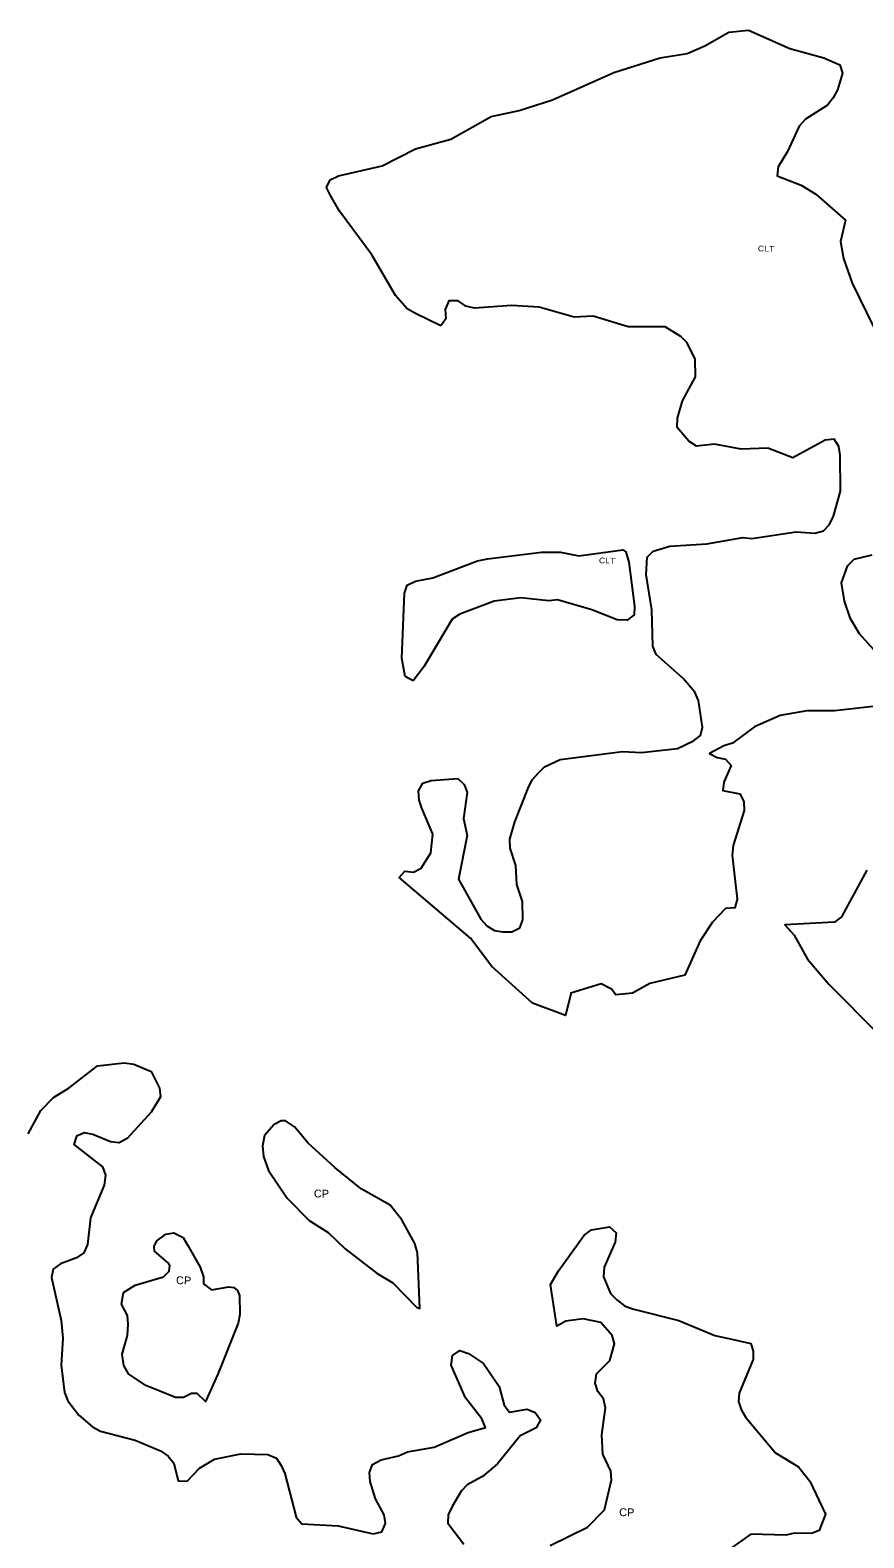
# Model space of a CAD drawing. Extents: x 713589 to 726391, y 7177764 to 7191819.
# Drawn here: x 715078 to 715761, y 7180236 to 7181472 of the extents above; entities that cross this region are included whole.
import ezdxf
from ezdxf.enums import TextEntityAlignment as Align

# ---------------------------------------------------------------- set-up
doc = ezdxf.new("R2010")
doc.units = 0
doc.header["$LTSCALE"] = 2.6
doc.layers.add('63', color=7, linetype='Continuous', lineweight=25)

msp = doc.modelspace()

# ---------------------------------------------------------------- linework, layer by layer
at = {"layer": '63'}
for points in [[(715414.63, 7181229.54), (715393.77, 7181239.84), (715387.14, 7181243.5), (715377.55, 7181254.45), (715358.05, 7181287.96), (715331.6, 7181323.79), (715324.33, 7181336.4), (715321.03, 7181343.03), (715324.02, 7181349.33), (715330.65, 7181352.63), (715366.46, 7181360.85), (715393.99, 7181374.73), (715422.84, 7181382.63), (715456.01, 7181401.14), (715478.88, 7181406.07), (715506.07, 7181414.98), (715556.49, 7181437.43), (715594.29, 7181449.3), (715616.5, 7181452.9), (715631.09, 7181459.18), (715650.66, 7181470.41), (715666.9, 7181472.04), (715700.68, 7181457.07), (715728.51, 7181449.4), (715741.76, 7181443.75), (715743.73, 7181436.79), (715739.73, 7181423.2), (715736.08, 7181416.58), (715731.43, 7181410.62), (715713.51, 7181399.05), (715708.2, 7181393.43), (715698.89, 7181372.57), (715691.24, 7181359.99), (715690.24, 7181352.7), (715710.11, 7181345.04), (715722.03, 7181337.73), (715746.3, 7181316.21), (715742.14, 7181298.78), (715744.77, 7181284.82), (715751.71, 7181264.54), (715769.26, 7181228.97)], [(715489.78, 7180674.55), (715456.36, 7180704.43), (715438.83, 7180727.66), (715380.58, 7180777.47), (715385.23, 7180782.76), (715392.19, 7180781.75), (715398.49, 7180785.06), (715406.47, 7180797.64), (715408.15, 7180812.88), (715399.14, 7180834.2), (715396.75, 7180840.82), (715396.43, 7180848.44), (715399.76, 7180854.73), (715406.72, 7180857.04), (715428.59, 7180858.66), (715433.89, 7180853.68), (715436.2, 7180847.05), (715433.18, 7180825.85), (715436.14, 7180811.92), (715429.12, 7180776.14), (715447.29, 7180743.3), (715452.26, 7180737.99), (715458.55, 7180734), (715465.5, 7180733), (715472.8, 7180732.98), (715479.43, 7180736.29), (715481.76, 7180742.91), (715481.45, 7180757.83), (715476.84, 7180771.75), (715476.2, 7180787.33), (715471.58, 7180801.59), (715471.26, 7180808.88), (715475.27, 7180823.12), (715486.25, 7180850.61), (715489.57, 7180857.57), (715494.55, 7180863.19), (715499.53, 7180868.16), (715512.47, 7180874.1), (715563.52, 7180880.64), (715579.09, 7180879.95), (715608.59, 7180883.22), (715621.86, 7180889.49), (715627.5, 7180893.79), (715629.17, 7180900.75), (715625.89, 7180922.63), (715622.92, 7180929.26), (715613.33, 7180940.55), (715591.16, 7180960.14), (715588.52, 7180967.1), (715587.57, 7180996.93), (715582.98, 7181025.77), (715583.67, 7181040.02), (715588.64, 7181044.98), (715602.24, 7181048.94), (715632.73, 7181050.87), (715662.24, 7181056.13), (715669.53, 7181055.45), (715705.99, 7181060.7), (715721.23, 7181059.68), (715728.2, 7181061.65), (715733.18, 7181066.95), (715736.5, 7181073.57), (715742.17, 7181094.11), (715741.89, 7181123.6), (715740.91, 7181130.9), (715736.94, 7181136.87), (715729.65, 7181135.89), (715703.11, 7181121.35), (715682.57, 7181129.34), (715660.7, 7181128.71), (715638.83, 7181132.72), (715624.25, 7181131.09), (715617.96, 7181135.08), (715608.37, 7181146.36), (715608.71, 7181153.98), (715612.71, 7181168.23), (715623.35, 7181187.76), (715623.04, 7181202.35), (715616.43, 7181215.61), (715611.47, 7181220.92), (715598.56, 7181228.9), (715568.07, 7181228.95), (715539.58, 7181237.61), (715524.01, 7181236.65), (715495.19, 7181244.98), (715472.65, 7181246.34), (715442.16, 7181244.07), (715435.2, 7181245.74), (715428.91, 7181250.06), (715421.29, 7181250.07), (715418.3, 7181243.12), (715418.61, 7181235.49), (715414.63, 7181229.54)], [(715767.93, 7181041.7), (715753.01, 7181038.08), (715747.7, 7181032.79), (715742.71, 7181018.88), (715745.33, 7181003.96), (715749.95, 7180990.36), (715757.55, 7180977.43), (715787.99, 7180943.24)], [(715774.02, 7180918.08), (715737.23, 7180914.16), (715714.7, 7180914.2), (715692.82, 7180910.26), (715671.59, 7180901.01), (715653.64, 7180887.55), (715646.69, 7180885.28), (715634.86, 7180879.08), (715641.06, 7180875.88), (715648.02, 7180874.54), (715652.65, 7180869.23), (715646.66, 7180855.65), (715645.65, 7180848.69), (715659.57, 7180846.02), (715662.87, 7180839.71), (715663.19, 7180832.42), (715654.2, 7180803.61), (715653.52, 7180795.65), (715657.44, 7180759.85), (715655.55, 7180752.71), (715647.98, 7180752.17), (715637.36, 7180740.92), (715627.06, 7180725.69), (715614.75, 7180697.54), (715585.91, 7180690.63), (715571.64, 7180682.7), (715558.05, 7180681.39), (715554.42, 7180686.04), (715546.14, 7180690.36), (715521.3, 7180682.79), (715521.07, 7180682.17), (715516.84, 7180664.4), (715489.78, 7180674.55)], [(715763.86, 7180783.54), (715742.92, 7180745.13), (715737.28, 7180740.83), (715696.57, 7180738.74), (715704.29, 7180730.2), (715715.19, 7180710.63), (715732.73, 7180690.05), (715772.43, 7180649.88)], [(715076.48, 7180567.27), (715086.79, 7180586.48), (715097.08, 7180597.07), (715110.02, 7180605), (715133.25, 7180623.19), (715155.12, 7180625.47), (715163.08, 7180624.46), (715177.32, 7180618.47), (715183.92, 7180604.87), (715184.91, 7180597.58), (715177.26, 7180585), (715157.67, 7180563.49), (715151.04, 7180559.86), (715143.75, 7180560.86), (715129.51, 7180566.85), (715122.55, 7180568.19), (715115.92, 7180565.55), (715113.92, 7180558.59), (715137.42, 7180540.33), (715139.73, 7180533.36), (715138.72, 7180525.41), (715127.41, 7180498.59), (715125.05, 7180476.72), (715122.06, 7180469.76), (715116.08, 7180465.79), (715102.82, 7180460.85), (715096.85, 7180456.55), (715095.51, 7180449.59), (715103.41, 7180414.45), (715104.71, 7180399.86), (715103.35, 7180377.66), (715106.29, 7180355.45), (715108.93, 7180348.49), (715117.86, 7180336.87), (715129.11, 7180327.24), (715135.73, 7180323.59), (715164.22, 7180316.25), (715184.76, 7180307.6), (715191.05, 7180303.28), (715195.68, 7180297.31), (715199.3, 7180283.05), (715206.59, 7180282.7), (715216.88, 7180293.29), (715229.15, 7180300.56), (715250.7, 7180305.17), (715272.91, 7180304.47), (715279.86, 7180301.47), (715283.83, 7180295.5), (715286.8, 7180288.87), (715296.02, 7180253.06), (715300.65, 7180247.75), (715330.48, 7180246.04), (715359.3, 7180239.37), (715366.26, 7180241.01), (715369.25, 7180247.97), (715368.27, 7180254.93), (715361, 7180268.2), (715356.72, 7180282.46), (715356.07, 7180289.75), (715358.73, 7180296.37), (715365.69, 7180300.01), (715379.95, 7180303.3)], [(715504.21, 7180229.93), (715534.75, 7180244.99), (715548.69, 7180259.21), (715554.57, 7180283.78), (715553.92, 7180290.75), (715547.32, 7180304.68), (715546.68, 7180320.58), (715549.7, 7180342.78), (715548.05, 7180350.08), (715543.42, 7180356.05), (715541.12, 7180363.01), (715542.12, 7180370.64), (715553.08, 7180381.55), (715557.08, 7180395.14), (715555.1, 7180402.1), (715545.84, 7180412.72), (715531.26, 7180415.73), (715517.01, 7180413.76), (715509.77, 7180409.75), (715504.59, 7180443.73), (715511.11, 7180455.2), (715532.04, 7180484.33), (715538.01, 7180488.63), (715552.93, 7180491.25), (715558.22, 7180486.27), (715557.55, 7180478.65), (715548.56, 7180458.12), (715547.89, 7180450.16), (715553.83, 7180436.57), (715558.79, 7180431.26), (715565.08, 7180426.27), (715571.71, 7180423.94), (715609.8, 7180414.27), (715639.28, 7180401.96), (715655.53, 7180398.37), (715668.85, 7180395.44), (715670.54, 7180389.31), (715670.53, 7180382.02), (715670.44, 7180381.8), (715659.22, 7180354.87), (715658.54, 7180347.91), (715660.85, 7180341.27), (715664.49, 7180334.97), (715688.96, 7180305.77), (715707.84, 7180294.47), (715717.1, 7180282.52), (715729.98, 7180255.66), (715724.65, 7180242.08), (715718.35, 7180239.77), (715704.43, 7180240.12), (715697.47, 7180238.48), (715668.64, 7180239.19), (715651.05, 7180226.62)], [(715379.95, 7180303.3), (715387.25, 7180306.6), (715409.13, 7180310.54), (715436.99, 7180322.42), (715451.24, 7180326.71), (715448.27, 7180333.67), (715434.71, 7180350.93), (715423.16, 7180377.79), (715424.17, 7180385.74), (715430.14, 7180389.71), (715437.42, 7180387.38), (715449.67, 7180379.07), (715462.57, 7180360.16), (715466.52, 7180344.91), (715470.82, 7180339.27), (715485.4, 7180341.57), (715492.03, 7180338.9), (715496.33, 7180332.93), (715492.67, 7180326.31), (715479.73, 7180319.7), (715461.14, 7180296.86), (715448.86, 7180286.61), (715436.25, 7180279.67), (715431.27, 7180274.38), (715423.96, 7180261.8), (715420.63, 7180255.17), (715420.29, 7180248.22), (715433.52, 7180230.96)]]:
    msp.add_lwpolyline(points, dxfattribs=at)
for points in [[(715391.94, 7180938.59), (715385.32, 7180942.25), (715382.69, 7180957.17), (715384.77, 7181010.52), (715387.1, 7181017.15), (715393.73, 7181020.45), (715407.99, 7181023.08), (715444.8, 7181036.94), (715452.75, 7181038.58), (715497.17, 7181044.14), (715512.75, 7181044.11), (715527.66, 7181041.11), (715563.79, 7181046.02), (715566.13, 7181044.34), (715568.75, 7181036.07), (715573.32, 7180999.94), (715572.98, 7180992.65), (715567.34, 7180988.35), (715559.06, 7180988.69), (715538.52, 7180997.01), (715510.37, 7181005.01), (715503.07, 7181004.36), (715480.21, 7181006.72), (715458.33, 7181004.1), (715430.14, 7180993.21), (715423.84, 7180989.25), (715400.58, 7180950.18)], [(715270.09, 7180566.09), (715268.42, 7180557.48), (715269.4, 7180548.86), (715273.36, 7180537.25), (715288.57, 7180514.69), (715306.76, 7180496.43), (715322.32, 7180486.46), (715336.22, 7180473.18), (715362.37, 7180452.92), (715375.28, 7180445.28), (715394.8, 7180425.36), (715397.53, 7180424.14), (715395.54, 7180469.77), (715393.23, 7180477.4), (715382.66, 7180496.97), (715373.07, 7180508.92), (715349.23, 7180522.21), (715327.71, 7180539.81), (715305.87, 7180559.73), (715294.63, 7180573.01), (715287.35, 7180577.99), (715283.7, 7180578), (715278.06, 7180575.02)], [(715154.71, 7180377.57), (715153.4, 7180386.86), (715157.74, 7180402.09), (715158.42, 7180411.37), (715157.76, 7180418.33), (715152.81, 7180427.62), (715154.48, 7180437.23), (715164.1, 7180443.18), (715187.31, 7180450.1), (715191.96, 7180454.73), (715192.63, 7180459.37), (715191.31, 7180461.36), (715180.06, 7180471.32), (715179.73, 7180474.97), (715181.73, 7180479.6), (715189.36, 7180485.23), (715195.66, 7180486.21), (715203.47, 7180482.43), (715207.24, 7180475.86), (715217.48, 7180458), (715220.12, 7180450.05), (715220.11, 7180444.41), (715226.73, 7180439.43), (715240.99, 7180442.06), (715244.96, 7180441.39), (715247.94, 7180439.06), (715249.59, 7180434.75), (715249.9, 7180419.17), (715248.56, 7180412.22), (715231.92, 7180370.49), (715221.61, 7180347.97), (715214.99, 7180354.61), (715210.35, 7180354.61), (715203.72, 7180351.31), (715197.09, 7180351.32), (715172.91, 7180360.97), (715158.68, 7180370.61)]]:
    msp.add_lwpolyline(points, close=True, dxfattribs=at)

# ---------------------------------------------------------------- texts
for s, height, width, p in [('CLT', 4.64, 1.15, (715681.2, 7181290.62)), ('CLT', 4.64, 1.15, (715550.9, 7181034.92)), ('CP', 6.4, 1.05, (715316.75, 7180515.17)), ('CP', 6.4, 1.05, (715203.78, 7180444.07)), ('CP', 6.4, 1.05, (715566.99, 7180253.95))]:
    msp.add_text(s, height=height, rotation=359.062, dxfattribs=dict(at, width=width)).set_placement(p, align=Align.CENTER)

doc.saveas('drawing.dxf')
